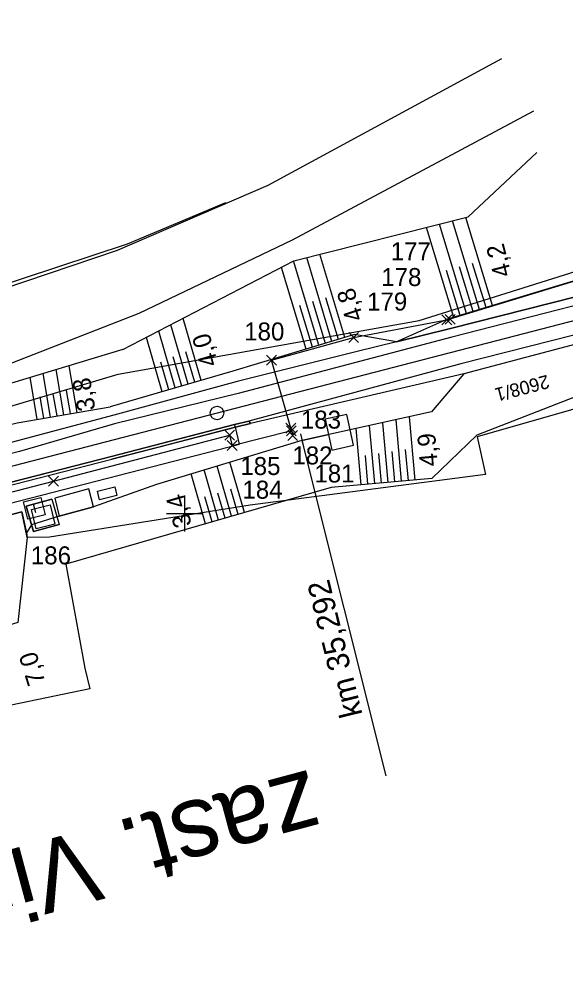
# Model space of a CAD drawing. Extents: x -806456 to -805395, y -1150847 to -1150506.
# Drawn here: x -806118.3 to -806057.6, y -1150752.4 to -1150645.1 of the extents above; entities that cross this region are included whole.
import ezdxf

# ---------------------------------------------------------------- set-up
doc = ezdxf.new("R2010")
doc.units = 0
for name, color, linetype in [('0381KM032-037P - Vrstva 1', 7, 'Continuous'), ('0381KM032-037P - Vrstva 14', 7, 'Continuous'), ('0381KM032-037P - Vrstva 16', 7, 'Continuous'), ('0381KM032-037P - Vrstva 17', 7, 'Continuous'), ('0381KM032-037P - Vrstva 23', 7, 'Continuous'), ('0381KM032-037P - Vrstva 25', 7, 'Continuous'), ('0381KM032-037P - Vrstva 33', 7, 'Continuous'), ('0381KM032-037P - Vrstva 4', 7, 'Continuous'), ('0381KM032-037P - Vrstva 48', 7, 'Continuous'), ('0381KM032-037P - Vrstva 49', 7, 'Continuous'), ('0381KM032-037P - Vrstva 51', 7, 'Continuous'), ('0381KM032-037P - Vrstva 57', 7, 'Continuous'), ('0381KM032-037P - Vrstva 7', 7, 'Continuous'), ('Default', 7, 'Continuous'), ('hran DP - hran DP', 7, 'Continuous'), ('krizky_1000 - Vrstva 1', 7, 'Continuous'), ('PSR_C2_2_Lomove_body_Vimperk - Vrstva 60', 7, 'Continuous'), ('PSR_C2_2_trasa_Vimperk - Kabelová trasa', 7, 'Continuous')]:
    doc.layers.add(name, color=color, linetype=linetype)

msp = doc.modelspace()

# ---------------------------------------------------------------- linework, layer by layer
at = {"layer": '0381KM032-037P - Vrstva 1'}
msp.add_lwpolyline([(-805989.76, -1150661.17), (-806027.03, -1150670.9), (-806064.32, -1150680.56), (-806101.67, -1150690.24), (-806138.44, -1150699.75), (-806158.28, -1150704.94), (-806163.64, -1150706.34), (-806175.38, -1150709.4), (-806186.46, -1150712.29), (-806205.2, -1150717.19), (-806213.26, -1150719.29)], dxfattribs=at)
at = {"layer": '0381KM032-037P - Vrstva 14'}
for p, q in [((-806094.31, -1150690.42), (-806094.43, -1150690.13)), ((-806093.88, -1150692.3), (-806094.31, -1150690.42)), ((-806092.84, -1150689.77), (-806092.67, -1150690)), ((-806161.45, -1150709.69), (-806093.88, -1150692.3))]:
    msp.add_line(p, q, dxfattribs=at)
for points in [[(-806154.89, -1150705.76), (-806154.2, -1150705.57), (-806132.57, -1150699.95), (-806108.13, -1150693.69), (-806094.43, -1150690.13), (-806092.84, -1150689.77), (-806094.43, -1150690.13), (-806108.12, -1150693.69), (-806132.57, -1150699.95), (-806154.2, -1150705.57), (-806154.88, -1150705.76)], [(-806154.82, -1150706.03), (-806154.13, -1150705.84), (-806132.47, -1150700.24), (-806108.06, -1150693.98), (-806094.31, -1150690.42), (-806092.67, -1150690)], [(-806092.67, -1150690), (-806094.31, -1150690.42), (-806103.16, -1150692.72), (-806108.06, -1150693.98)]]:
    msp.add_lwpolyline(points, dxfattribs=at)
at = {"layer": '0381KM032-037P - Vrstva 16'}
for q in [(-806113.93, -1150701.24), (-806113.94, -1150701.24)]:
    msp.add_line((-806114.72, -1150698.42), q, dxfattribs=at)
for points in [[(-806114.72, -1150698.42), (-806114.72, -1150698.42), (-806117.58, -1150699.2), (-806117.58, -1150699.2), (-806114.72, -1150698.42)], [(-806117.58, -1150699.2), (-806116.77, -1150702.02), (-806116.77, -1150702.02), (-806117.58, -1150699.2)], [(-806116.77, -1150702.02), (-806113.94, -1150701.24), (-806113.93, -1150701.24), (-806116.77, -1150702.02)]]:
    msp.add_lwpolyline(points, dxfattribs=at)
at = {"layer": '0381KM032-037P - Vrstva 17'}
for points in [[(-806169.28, -1150696.91), (-806165.68, -1150693.97), (-806155.41, -1150686.94), (-806141.03, -1150680.9), (-806121.85, -1150675.14), (-806106.33, -1150670.05), (-806095.39, -1150665.45)], [(-806136.29, -1150704.55), (-806118.08, -1150699.83), (-806117.57, -1150702.15), (-806117.47, -1150702.7)]]:
    msp.add_lwpolyline(points, dxfattribs=at)
at = {"layer": '0381KM032-037P - Vrstva 23'}
for p, q in [((-806110.63, -1150697.29), (-806114.4, -1150698.3)), ((-806110.1, -1150699.27), (-806110.63, -1150697.29)), ((-806116.98, -1150699.59), (-806114.92, -1150699.04)), ((-806114.4, -1150698.3), (-806113.94, -1150700.3)), ((-806116.46, -1150701.73), (-806116.98, -1150699.59)), ((-806113.94, -1150700.3), (-806110.1, -1150699.27))]:
    msp.add_line(p, q, dxfattribs=at)
msp.add_lwpolyline([(-806114.92, -1150699.04), (-806114.39, -1150701.22), (-806116.46, -1150701.73)], dxfattribs=at)
at = {"layer": '0381KM032-037P - Vrstva 25'}
msp.add_lwpolyline([(-806109.45, -1150698.49), (-806109.68, -1150697.52), (-806107.74, -1150697.05), (-806107.5, -1150698.02), (-806109.45, -1150698.49)], dxfattribs=at)
at = {"layer": '0381KM032-037P - Vrstva 33'}
for p, q in [((-806117.29, -1150699.08), (-806116.32, -1150698.83)), ((-806116.8, -1150698.95), (-806116.55, -1150699.92))]:
    msp.add_line(p, q, dxfattribs=at)
msp.add_lwpolyline([(-806117.9, -1150698.72), (-806115.96, -1150698.22), (-806115.46, -1150700.16), (-806117.4, -1150700.66), (-806117.9, -1150698.72)], dxfattribs=at)
at = {"layer": '0381KM032-037P - Vrstva 4'}
msp.add_line((-806068.97, -1150684.48), (-806092.67, -1150690), dxfattribs=at)
for points in [[(-805920.59, -1150645.08), (-805938.49, -1150646.69), (-805957, -1150650.24), (-805973.18, -1150654.13), (-805996.94, -1150660.52), (-806010.57, -1150664.04), (-806045.29, -1150673.07), (-806070.44, -1150679.45), (-806076.44, -1150680.94), (-806080.95, -1150682.04), (-806094.16, -1150685.34), (-806107.83, -1150689.09)], [(-805923.83, -1150646.61), (-805939.39, -1150648.49), (-805956.78, -1150651.56), (-805972.77, -1150655.27), (-805996.74, -1150661.47), (-806010.38, -1150665.11), (-806045.15, -1150673.98), (-806070.28, -1150680.43), (-806094.02, -1150686.67), (-806107.78, -1150690.05)], [(-805923.37, -1150650.9), (-805938.15, -1150652.42), (-805956.35, -1150655.74), (-805972.37, -1150659.35), (-805995.12, -1150665.03), (-806009.04, -1150668.86), (-806027.1, -1150673.31), (-806034.62, -1150675.7), (-806043.91, -1150677.85), (-806068.97, -1150684.48)], [(-805995.68, -1150664.21), (-806009.49, -1150668.04), (-806044.17, -1150677), (-806069.3, -1150683.37)], [(-806069.3, -1150683.37), (-806092.84, -1150689.77), (-806092.67, -1150690)], [(-806107.83, -1150689.09), (-806118.69, -1150691.97), (-806137.28, -1150697.2), (-806151.73, -1150700.28), (-806152.97, -1150701.48)], [(-806107.78, -1150690.05), (-806118.34, -1150693.12), (-806137.19, -1150697.81), (-806152.97, -1150701.48)]]:
    msp.add_lwpolyline(points, dxfattribs=at)
at = {"layer": '0381KM032-037P - Vrstva 48'}
for p, q in [((-806068.65, -1150677.78), (-806071.66, -1150667.84)), ((-806067.21, -1150677.34), (-806070.2, -1150667.47)), ((-806065.78, -1150676.91), (-806068.75, -1150667.1)), ((-806070.08, -1150678.21), (-806073.11, -1150668.21)), ((-806082.18, -1150680.45), (-806084.96, -1150671.2)), ((-806085.05, -1150681.32), (-806087.87, -1150671.94)), ((-806083.61, -1150680.89), (-806086.41, -1150671.57)), ((-806066.49, -1150677.12), (-806067.98, -1150672.21)), ((-806086.49, -1150681.75), (-806089.22, -1150672.65)), ((-806069.37, -1150678), (-806070.88, -1150673.01)), ((-806067.93, -1150677.56), (-806069.43, -1150672.61)), ((-806084.33, -1150681.1), (-806085.74, -1150676.43)), ((-806082.9, -1150680.67), (-806084.29, -1150676.03)), ((-806085.77, -1150681.53), (-806087.16, -1150676.91)), ((-806098.14, -1150685.22), (-806100.15, -1150678.32)), ((-806101.02, -1150686.06), (-806102.86, -1150679.73)), ((-806099.58, -1150685.64), (-806101.51, -1150679.03)), ((-806102.46, -1150686.48), (-806104.22, -1150680.44)), ((-806100.3, -1150685.85), (-806101.24, -1150682.61)), ((-806098.86, -1150685.43), (-806099.85, -1150682.05)), ((-806113.41, -1150689.04), (-806114.26, -1150684.02)), ((-806111.93, -1150688.79), (-806112.81, -1150683.59)), ((-806101.74, -1150686.27), (-806102.64, -1150683.18)), ((-806116.36, -1150689.54), (-806117.16, -1150684.89)), ((-806114.89, -1150689.29), (-806115.71, -1150684.46)), ((-806115.63, -1150689.42), (-806116.03, -1150687.05)), ((-806114.15, -1150689.16), (-806114.57, -1150686.7)), ((-806112.67, -1150688.91), (-806113.1, -1150686.36)), ((-806074.38, -1150696.3), (-806074.99, -1150689.27)), ((-806078.86, -1150696.69), (-806079.42, -1150690.24)), ((-806077.37, -1150696.56), (-806077.94, -1150689.92)), ((-806075.87, -1150696.43), (-806076.46, -1150689.59)), ((-806080.35, -1150696.82), (-806080.9, -1150690.56)), ((-806079.61, -1150696.76), (-806079.88, -1150693.58)), ((-806078.11, -1150696.63), (-806078.4, -1150693.35)), ((-806076.62, -1150696.5), (-806076.91, -1150693.13)), ((-806075.12, -1150696.37), (-806075.43, -1150692.9)), ((-806094.76, -1150700.32), (-806096.38, -1150694.75)), ((-806093.32, -1150699.9), (-806094.94, -1150694.31)), ((-806097.65, -1150701.15), (-806099.25, -1150695.62)), ((-806096.21, -1150700.74), (-806097.81, -1150695.18)), ((-806095.48, -1150700.53), (-806096.29, -1150697.75)), ((-806094.04, -1150700.11), (-806094.85, -1150697.32)), ((-806096.93, -1150700.94), (-806097.73, -1150698.17))]:
    msp.add_line(p, q, dxfattribs=at)
at = {"layer": '0381KM032-037P - Vrstva 49'}
for points in [[(-806076.44, -1150680.94), (-806070.44, -1150679.45), (-806045.29, -1150673.07), (-806010.57, -1150664.04), (-805996.94, -1150660.52), (-805973.18, -1150654.13), (-805957, -1150650.24), (-805938.49, -1150646.69)], [(-806106.83, -1150681.79), (-806087.86, -1150671.94), (-806068.49, -1150667.04), (-806060.84, -1150659.9)], [(-805995.12, -1150665.03), (-806009.04, -1150668.86), (-806027.1, -1150673.31), (-806034.62, -1150675.7), (-806043.91, -1150677.85), (-806068.97, -1150684.48)], [(-806046.76, -1150671.15), (-806070.76, -1150678.42)], [(-806070.76, -1150678.42), (-806076.44, -1150680.94), (-806081.09, -1150680.13), (-806094.64, -1150684.2), (-806108.26, -1150688.17)], [(-806042.38, -1150685.77), (-806037.14, -1150679.5), (-806067.5, -1150691.31), (-806072.52, -1150696.14), (-806083.69, -1150697.11)], [(-806106.83, -1150681.79), (-806120.86, -1150686.01), (-806130.84, -1150689.2), (-806140.72, -1150692.22), (-806149.98, -1150695.47), (-806155.41, -1150698.65)], [(-806068.97, -1150684.48), (-806072.55, -1150688.73), (-806086.94, -1150691.89)], [(-806155.86, -1150700.93), (-806155.37, -1150700.64), (-806154.96, -1150699.45), (-806154.58, -1150699.23), (-806153.89, -1150698.71), (-806149.38, -1150697.67), (-806139.49, -1150695.22), (-806130.93, -1150692.92), (-806118.59, -1150689.92), (-806108.26, -1150688.17)], [(-806086.94, -1150691.89), (-806103.09, -1150696.78), (-806110.1, -1150699.27), (-806113.94, -1150700.3), (-806116.98, -1150701.29), (-806117.57, -1150702.15), (-806117.47, -1150702.7), (-806118.52, -1150712.15), (-806144.33, -1150720.15), (-806155.42, -1150722.6), (-806156.37, -1150719.96), (-806156.92, -1150718.66), (-806157.56, -1150717.45), (-806160.48, -1150717.28), (-806160.29, -1150717.98), (-806160.2, -1150718.76), (-806166.07, -1150720.05), (-806166.41, -1150718.42)], [(-806083.69, -1150697.11), (-806113.19, -1150705.65), (-806111.06, -1150717.22), (-806110.51, -1150719.49), (-806126.08, -1150722.72), (-806134.13, -1150725.52)]]:
    msp.add_lwpolyline(points, dxfattribs=at)
at = {"layer": '0381KM032-037P - Vrstva 51'}
for points in [[(-806140.16, -1150681.15), (-806120.15, -1150675.05), (-806107.44, -1150670.76), (-806090.7, -1150663.5), (-806064.75, -1150649.45)], [(-806121.48, -1150684.16), (-806105.03, -1150677.76), (-806088.01, -1150669.6), (-806061.17, -1150655.26)]]:
    msp.add_lwpolyline(points, dxfattribs=at)
at = {"layer": '0381KM032-037P - Vrstva 7'}
for p, q in [((-806087.1, -1150691.15), (-806086.78, -1150692.62)), ((-806086.94, -1150691.89), (-806077.64, -1150729.17))]:
    msp.add_line(p, q, dxfattribs=at)
msp.add_lwpolyline([(-806086.94, -1150691.89), (-806084.01, -1150691.25), (-806083.64, -1150692.96), (-806081.2, -1150692.43), (-806081.94, -1150689.01), (-806084.38, -1150689.54), (-806084.01, -1150691.25)], dxfattribs=at)
msp.add_circle((-806096.38, -1150688.84), 0.75, dxfattribs=at)
at = {"layer": 'hran DP - hran DP'}
for p, q in [((-806073.91, -1150678.57), (-806039.45, -1150667.69)), ((-806107.35, -1150684.54), (-806073.91, -1150678.57)), ((-806152.11, -1150697.83), (-806107.35, -1150684.54)), ((-806051.33, -1150686.88), (-806067.49, -1150691.49)), ((-806067.49, -1150691.49), (-806066.55, -1150695.68)), ((-806066.55, -1150695.68), (-806092.7, -1150699.08)), ((-806092.7, -1150699.08), (-806114.99, -1150702.66)), ((-806118.08, -1150699.83), (-806136.29, -1150704.55)), ((-806117.47, -1150702.7), (-806118.08, -1150699.83)), ((-806114.99, -1150702.66), (-806117.47, -1150702.7))]:
    msp.add_line(p, q, dxfattribs=at)
at = {"layer": 'krizky_1000 - Vrstva 1'}
for points in [[(-806100, -1150698), (-806100, -1150702)], [(-806102, -1150700), (-806098, -1150700)]]:
    msp.add_lwpolyline(points, dxfattribs=at)
at = {"layer": 'PSR_C2_2_Lomove_body_Vimperk - Vrstva 60'}
for p, q in [((-806071.39, -1150679.04), (-806070.29, -1150677.94)), ((-806070.29, -1150679.04), (-806071.39, -1150677.94)), ((-806071.03, -1150678.98), (-806069.93, -1150677.88)), ((-806069.93, -1150678.98), (-806071.03, -1150677.88)), ((-806081.75, -1150681), (-806080.65, -1150679.9)), ((-806080.65, -1150681), (-806081.75, -1150679.9)), ((-806090.87, -1150683.51), (-806089.77, -1150682.41)), ((-806089.77, -1150683.51), (-806090.87, -1150682.41)), ((-806088.74, -1150691.08), (-806087.64, -1150689.98)), ((-806087.64, -1150691.08), (-806088.74, -1150689.98)), ((-806088.67, -1150691.38), (-806087.57, -1150690.28)), ((-806087.57, -1150691.38), (-806088.67, -1150690.28)), ((-806095.53, -1150691.85), (-806094.43, -1150690.75)), ((-806094.43, -1150691.85), (-806095.53, -1150690.75)), ((-806088.53, -1150691.89), (-806087.43, -1150690.79)), ((-806087.43, -1150691.89), (-806088.53, -1150690.79)), ((-806095.25, -1150693), (-806094.15, -1150691.9)), ((-806094.15, -1150693), (-806095.25, -1150691.9)), ((-806115.09, -1150696.98), (-806113.99, -1150695.88)), ((-806113.99, -1150696.98), (-806115.09, -1150695.88))]:
    msp.add_line(p, q, dxfattribs=at)
at = {"layer": 'PSR_C2_2_trasa_Vimperk - Kabelová trasa'}
for q in [(-806090.32, -1150682.96), (-806087.98, -1150691.34)]:
    msp.add_line((-806088.19, -1150690.53), q, dxfattribs=at)
for points in [[(-806070.84, -1150678.49), (-806046.76, -1150671.15), (-806021.98, -1150665.32)], [(-806090.32, -1150682.96), (-806081.2, -1150680.45), (-806070.48, -1150678.43)], [(-806165.37, -1150711.96), (-806160.98, -1150708.44), (-806114.54, -1150696.43), (-806094.98, -1150691.3), (-806094.7, -1150692.45)], [(-806094.7, -1150692.45), (-806088.12, -1150690.8)]]:
    msp.add_lwpolyline(points, dxfattribs=at)

# ---------------------------------------------------------------- texts
at = {"layer": '0381KM032-037P - Vrstva 23'}
msp.add_text('zast. Vimperk', height=8, rotation=195, dxfattribs=at).set_placement((-806086.07, -1150728.44))
at = {"layer": '0381KM032-037P - Vrstva 48'}
for s, rotation, p in [('4,2', 104.1997, (-806063.65, -1150673.47)), ('4,8', 108.036, (-806080.07, -1150678.31)), ('4,0', 106.2287, (-806096.24, -1150683.39)), ('3,8', 99.6413, (-806109.88, -1150688.46)), ('4,9', 94.9542, (-806071.83, -1150694.71)), ('3,4', 106.1463, (-806099.15, -1150701.26)), ('7,0', 107.0974, (-806115.43, -1150718.78))]:
    msp.add_text(s, height=2, rotation=rotation, dxfattribs=at).set_placement(p)
at = {"layer": '0381KM032-037P - Vrstva 57'}
msp.add_text('2608/1', height=1.5, rotation=194.7572, dxfattribs=at).set_placement((-806059.69, -1150684.58))
at = {"layer": '0381KM032-037P - Vrstva 7'}
msp.add_text('km 35,292', height=2.5, rotation=103.9101, dxfattribs=at).set_placement((-806080.2, -1150722.36))
at = {"layer": 'Default'}
for s, p in [('177', (-806077.08, -1150671.86)), ('178', (-806078.13, -1150674.73)), ('179', (-806079.71, -1150677.45)), ('180', (-806093.36, -1150680.78)), ('183', (-806087.06, -1150690.58)), ('182', (-806088.01, -1150694.56)), ('185', (-806093.79, -1150695.74)), ('181', (-806085.56, -1150696.57)), ('184', (-806093.56, -1150698.37)), ('186', (-806117.07, -1150705.67))]:
    msp.add_text(s, height=2, dxfattribs=at).set_placement(p)

doc.saveas('drawing.dxf')
